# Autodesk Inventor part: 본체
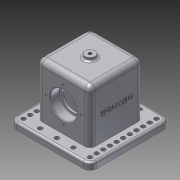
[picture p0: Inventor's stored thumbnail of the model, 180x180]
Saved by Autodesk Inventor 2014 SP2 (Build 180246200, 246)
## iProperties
Created: 2018-11
Part Number: 본체
Material: 알루미늄 6061
Document SubType Name: Modeling
Designer: 거성
Density: 2.71 g/cm^3
Appearance: 알루미늄 - 평지
Mass: 1019.13 g
Surface Area: 780.986 cm^2
Volume: 376.063 cm^3
Author: 거성
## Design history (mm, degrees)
sketch "스케치1"
  geometry: L1 (40, -40)-(-40, -40); L2 (-40, -40)-(-40, 40); L3 (-40, 40)-(40, 40); L4 (40, 40)-(40, -40); L5 (40, -40)-(-40, 40); L6 (-40, -40)-(40, 40); 1 further point
  constraints: 12 end point, 2 midpoint, 2 parallel, 1 horizontal, 1 perpendicular
  dimensions: "d0" = 80 distance of L2.end L3.end; "d1" = 80 distance of L1.end L2.end
extrude "돌출1" new body sketch "스케치1" distance "d2" = 90; taper "d3" = 0 deg
sketch "스케치2"
  geometry: L1 (-40, -40)-(40, -40) reference; L2 (40, -40)-(40, 40) reference; L3 (40, 40)-(-40, 40) reference; L4 (-40, 40)-(-40, -40) reference; L5 (-60, 60)-(60, 60); L6 (60, 60)-(60, -60); L7 (60, -60)-(-60, -60); L8 (-60, -60)-(-60, 60); L9 (-60, 60)-(60, -60); L10 (60, 60)-(-60, -60); 1 further point
  constraints: 12 end point, 2 midpoint, 2 parallel, 1 horizontal, 1 perpendicular
  dimensions: "d4" = 120 distance of L6.end L7.end; "d5" = 120 distance of L5.end L6.end
extrude "돌출2" join sketch "스케치2" distance "d6" = 10; taper "d7" = 0 deg
fillet "모깎기1" dims "d8" = 8
fillet "모깎기2" dims "d9" = 10
fillet "모깎기3" dims "d10" = 3
sketch "스케치3"
  geometry: L1 (50, -57)-(-50, -57) reference; L2 (57, 50)-(57, -50) reference; C1 r 3.3 at (-25, -50); C2 r 3.3 at (0, -50); C3 r 3.3 at (25, -50); A1 r 7 centre (-50, -50) between (-57, -50) and (-50, -57) reference; 11 further points
  constraints: 3 centre point, 1 coincident
  dimensions: "d41" = 6.6 diameter of C1; "d43" = 6.6 diameter of C2; "d45" = 6.6 diameter of C3; "d56" = 32 distance from line of C3.centre L2; "d57" = 7 distance from line of C3.centre L1; "d58" = 57 distance from line of C2.centre L2; "d59" = 7 distance from line of C2.centre L1; "d60" = 82 distance from line of C1.centre L2; "d61" = 7 distance from line of C1.centre L1; "d62" = 107 distance from line of point (-50, 40) L2; "d63" = 97 distance from line of point (-50, 40) L1; "d64" = 107 distance from line of point (-50, 30) L2; "d65" = 87 distance from line of point (-50, 30) L1; "d66" = 107 distance from line of point (-50, 20) L2; "d67" = 77 distance from line of point (-50, 20) L1; "d68" = 107 distance from line of point (-50, 10) L2; "d69" = 67 distance from line of point (-50, 10) L1; "d70" = 107 distance from line of point (-50, 0) L2; "d71" = 57 distance from line of point (-50, 0) L1; "d72" = 107 distance from line of point (-50, -10) L2; "d73" = 47 distance from line of point (-50, -10) L1; "d74" = 107 distance from line of point (-50, -20) L2; "d75" = 37 distance from line of point (-50, -20) L1; "d76" = 107 distance from line of point (-50, -30) L2; "d77" = 27 distance from line of point (-50, -30) L1; "d78" = 107 distance from line of point (-50, -40) L2; "d79" = 17 distance from line of point (-50, -40) L1
hole "구멍1" sketch "스케치3" diameter "d80" = 6.6; stored, may be unused: countersink angle "d84" = 90 deg, drill point angle "d86" = 118 deg; dims "d81" = 6, "d82" = 4, "d83" = 2, "d85" = 8
sketch "스케치4"
  geometry: A1 r 7 centre (-50, 50) between (-50, 57) and (-57, 50) reference; 2 further points
  constraints: 1 coincident
hole "구멍2" sketch "스케치4" at (-50, 50) diameter "d87" = 6.6; stored, may be unused: countersink angle "d91" = 90 deg, drill point angle "d93" = 118 deg; dims "d88" = 6, "d89" = 4, "d90" = 2, "d92" = 8
hole "구멍3" sketch "스케치3" diameter "d94" = 6.6; stored, may be unused: countersink angle "d98" = 90 deg, drill point angle "d100" = 118 deg; dims "d95" = 6, "d96" = 4, "d97" = 2, "d99" = 8
sketch "스케치5"
  geometry: L1 (30, 23)-(-30, 23); L2 (-30, 23)-(-30, -23); L3 (-30, -23)-(30, -23); L4 (30, -23)-(30, 23); L5 (30, 23)-(-30, -23); L6 (-30, 23)-(30, -23); 1 further point
  constraints: 12 end point, 2 midpoint, 2 parallel, 1 horizontal, 1 perpendicular
  dimensions: "d101" = 60 distance of L3.end L2.end; "d102" = 46 distance of L2.end L1.end
extrude "돌출3" cut sketch "스케치5" distance "d103" = 80; taper "d104" = 0 deg
fillet "모깎기4" dims "d105" = 3
fillet "모깎기5" dims "d106" = 3
fillet "모깎기6" dims "d107" = 8
sketch "스케치6"
  geometry: L1 (0, 46.7)-(10, 46.7) reference; L2 (10, 46.7)-(10, 40) reference; L3 (10, 40)-(82, 40) reference; L4 (90, 32)-(90, -32) reference; L5 (82, -40)-(10, -40) reference; L6 (10, -40)-(10, -46.7) reference; L7 (10, -46.7)-(0, -46.7) reference; L8 (0, -46.7)-(0, -23) reference; L9 (0, -23)-(77, -23) reference; L10 (80, -20)-(80, 20) reference; L11 (77, 23)-(0, 23) reference; L12 (0, 23)-(0, 46.7) reference; L13 (10, 57)-(10, 53.3) reference; L14 (10, 53.3)-(0, 53.3) reference; L15 (0, 53.3)-(0, 60) reference; L16 (0, 60)-(7, 60) reference; L17 (7, -60)-(0, -60) reference; L18 (0, -60)-(0, -53.3) reference; L19 (0, -53.3)-(10, -53.3) reference; L20 (10, -53.3)-(10, -57) reference; L21 (0, 0)-(48, 0); L22 (48, 40)-(48, -40); L23 (48, 40)-(68, 40); L24 (68, 40)-(68, 26.6); L25 (67.4, 26)-(48, 26); A1 r 8 centre (82, 32) between (90, 32) and (82, 40) reference; A2 r 8 centre (82, -32) between (82, -40) and (90, -32) reference; A3 r 3 centre (77, -20) between (77, -23) and (80, -20) reference; A4 r 3 centre (77, 20) between (80, 20) and (77, 23) reference; A5 r 3 centre (7, 57) between (10, 57) and (7, 60) reference; A6 r 3 centre (7, -57) between (7, -60) and (10, -57) reference; A7 r 0.6 centre (67.4, 26.6) between (67.4, 26) and (68, 26.6); 1 further point
  constraints: 10 end point, 4 perpendicular, 4 point on line, 2 point on circle, 2 tangent, 1 centre point, 1 midpoint
  dimensions: "d108" = 48 distance of L21.end L21.start; "d110" = 80 distance of L22.start L22.end; "d111" = 14 distance of L23.end point (68, 26); "d112" = 0.6 radius of A7; "d113" = 40 diameter of L23.end L22
revolve "회전1" sketch "스케치6" stored, may be unused: angle "d114" = 90 deg
chamfer "모따기1" distance "d115" = 1; stored, may be unused: second distance "d116" = 2, angle "d117" = 45 deg
sketch "스케치7"
  geometry: C1 r 19.4 at (0, 0) reference; C2 r 16.5 at (0, 0); 1 further point
  constraints: 1 centre point, 1 coincident
  dimensions: "d118" = 33 diameter of C2
extrude "돌출4" cut sketch "스케치7" stored distance "d119" = 80; taper "d120" = 0 deg
sketch "스케치8"
  geometry: 1 further point
sketch "스케치9" dims "d121" = 52
  geometry: C1 r 21 at (32, 38) reference; 3 further points
  constraints: 1 coincident, 1 vertical alignment, 2 other
hole "구멍4" sketch "스케치9" at (32, 64) diameter "d122" = 3.242; stored, may be unused: countersink angle "d126" = 90 deg, drill point angle "d128" = 118 deg; dims "d123" = 8, "d124" = 4, "d125" = 2, "d127" = 10
node "작업 평면1"
sketch "스케치11"
  geometry: C1 r 7.5 at (0, 0); 1 further point
  constraints: 1 centre point, 1 coincident
  dimensions: "d133" = 15 diameter of C1
extrude "돌출5" join sketch "스케치11" stored distance "d134" = 25; taper "d135" = 0 deg
fillet "모깎기7" dims "d136" = 3
sketch "스케치12"
  geometry: C1 r 7.5 at (0, 0) reference; 1 further point
  constraints: 1 coincident
hole "구멍5" sketch "스케치12" at (0, 0) diameter "d137" = 4.917; stored, may be unused: countersink angle "d141" = 90 deg, drill point angle "d143" = 118 deg; dims "d138" = 40, "d139" = 4, "d140" = 2, "d142" = 10
sketch "스케치13"
  geometry: L1 (0, 72)-(64, 72) reference; L2 (-18, -10)-(82, -10) reference; L3 (92, -10)-(82, -10) reference; L4 (82, 0)-(-18, 0) reference; 3 further points
  constraints: 1 midpoint, 1 vertical alignment, 1 other
  dimensions: "d144" = 48 distance from line of L3 point (32, 38)
feature "엠보싱1" sketch "스케치13" dims "d0" = 80, "d1" = 80, "d145" = 0.5, "d146" = 0
node "솔리드1"
mirror "대칭1"
mirror "대칭2"
mirror "대칭3"
pattern_circular "원형 패턴1" dims angle "d130" = 360 deg
mirror "대칭4"
node "절단 모서리 투영1"
other parameters: "d132" = 5
